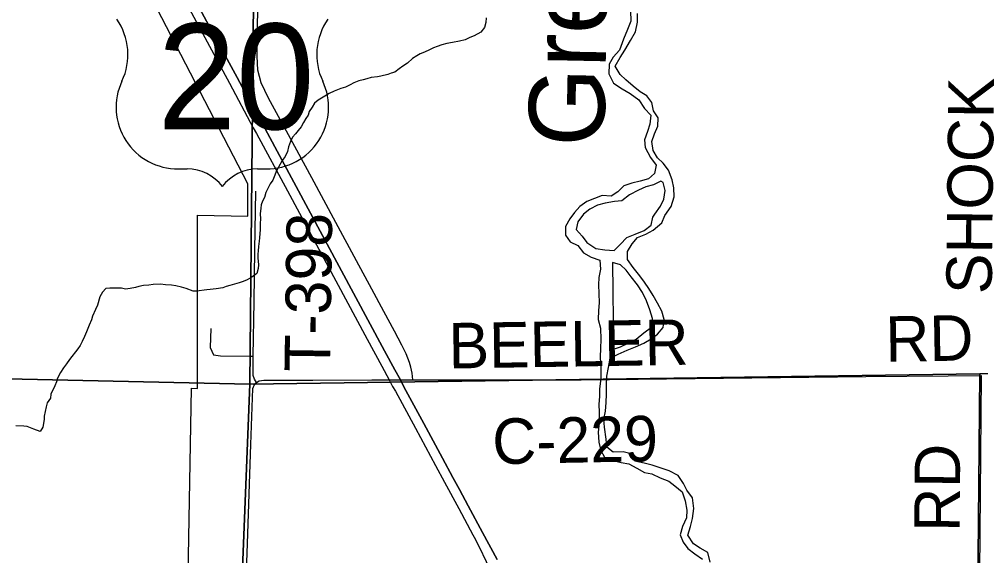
# Model space of a CAD drawing. Extents: x 0 to 34, y 0 to 22.
# Drawn here: x 25.81 to 27.011, y 19.609 to 20.279 of the extents above; entities that cross this region are included whole.
import ezdxf

# ---------------------------------------------------------------- set-up
doc = ezdxf.new("R2010")
doc.units = 0
for name, color, linetype in [('GM_X_City_Street', 7, 'Continuous'), ('GM_X_County_Road', 7, 'Continuous'), ('GM_X_County_Road_Text', 7, 'Continuous'), ('GM_X_Minor_River', 7, 'Continuous'), ('GM_X_Minor_River_Text', 7, 'Continuous'), ('GM_X_Section', 7, 'Continuous'), ('GM_X_State_Route', 7, 'Continuous'), ('GM_X_Township_Road', 7, 'Continuous'), ('GM_X_Township_Road_Text', 7, 'Continuous'), ('GM_X_US_Location', 7, 'Continuous'), ('GM_X_US_Route', 7, 'Continuous'), ('GM_X_US_Shield', 7, 'Continuous')]:
    doc.layers.add(name, color=color, linetype=linetype)

msp = doc.modelspace()

# ---------------------------------------------------------------- linework, layer by layer
at = {"layer": 'GM_X_City_Street'}
msp.add_lwpolyline([(25.7608, 19.5385), (26.0181, 19.4449), (26.0246, 19.8182), (26.0322, 19.818), (26.0322, 20.0343), (26.0952, 20.0332), (26.0952, 20.0736), (25.9699, 20.3158)], dxfattribs=at)
at = {"layer": 'GM_X_County_Road'}
for points in [[(26.301, 19.8288), (26.3002, 19.8371), (26.2987, 19.8445), (26.2969, 19.8503), (26.2927, 19.8612), (26.2875, 19.8718), (26.2782, 19.8896), (26.2651, 19.9141), (26.25, 19.9419), (26.2307, 19.9774), (26.2049, 20.0253), (26.1749, 20.0809), (26.146, 20.1344), (26.121, 20.1805), (26.1119, 20.1994), (26.1076, 20.2154), (26.1067, 20.2326), (26.1076, 20.2958)], [(26.301, 19.8288), (26.5115, 19.8289), (26.8669, 19.8327), (26.9698, 19.8338), (27.0117, 19.8339)], [(26.0866, 19.4072), (26.089, 19.4486), (26.0905, 19.5054), (26.0945, 19.6244), (26.0989, 19.7481), (26.1013, 19.8177), (26.1022, 19.82)], [(26.1022, 19.82), (26.1025, 19.8208), (26.103, 19.8219), (26.106, 19.8254), (26.1091, 19.8275), (26.1149, 19.8284), (26.1762, 19.8284), (26.2498, 19.8286), (26.2717, 19.8289), (26.2857, 19.8286), (26.301, 19.8288)]]:
    msp.add_lwpolyline(points, dxfattribs=at)
at = {"layer": 'GM_X_Minor_River'}
msp.add_line((26.5505, 19.9752), (26.5517, 19.8669), dxfattribs=at)
for points in [[(26.573, 20.2893), (26.5734, 20.2764), (26.5693, 20.2659), (26.5641, 20.2542), (26.5592, 20.2403), (26.5513, 20.2314), (26.5465, 20.2228), (26.5458, 20.2107), (26.552, 20.1991), (26.5628, 20.192), (26.5725, 20.186), (26.5833, 20.1782), (26.5905, 20.1673), (26.5983, 20.1591), (26.5972, 20.1478), (26.5943, 20.1387), (26.5906, 20.1282), (26.5915, 20.1187), (26.598, 20.1064), (26.6053, 20.0967), (26.6032, 20.0865), (26.5954, 20.0795), (26.5851, 20.0767), (26.5748, 20.0743), (26.5648, 20.0708), (26.5574, 20.0634), (26.5489, 20.058), (26.5376, 20.059), (26.528, 20.0551), (26.5184, 20.0512), (26.5099, 20.045), (26.5029, 20.0376), (26.4973, 20.0298), (26.4918, 20.0201), (26.4919, 20.0094), (26.4977, 20.0009), (26.5074, 19.9965), (26.5144, 19.9872), (26.5241, 19.982), (26.5346, 19.9782), (26.5354, 19.9668), (26.5337, 19.9566), (26.533, 19.9472), (26.5335, 19.9365), (26.5339, 19.9247), (26.5329, 19.9153), (26.5326, 19.9039), (26.5354, 19.8932), (26.5361, 19.8791), (26.5354, 19.8681), (26.5351, 19.8571), (26.5359, 19.843), (26.5359, 19.8305), (26.5344, 19.8176), (26.5342, 19.8082), (26.5335, 19.7979), (26.534, 19.7884), (26.5341, 19.7751)], [(26.3929, 20.2807), (26.3924, 20.275), (26.3905, 20.2686), (26.3862, 20.2626), (26.3778, 20.2581), (26.3725, 20.2563), (26.3664, 20.2533), (26.3595, 20.2515), (26.3508, 20.2497), (26.3436, 20.2486), (26.3375, 20.2468), (26.3314, 20.2449), (26.3268, 20.2431), (26.3219, 20.2409), (26.3158, 20.2379), (26.3104, 20.2357), (26.3062, 20.2331), (26.3009, 20.2301), (26.2947, 20.2241), (26.2886, 20.2203), (26.284, 20.217), (26.2787, 20.2128), (26.2741, 20.2114), (26.2699, 20.2099), (26.2612, 20.2077), (26.257, 20.207), (26.249, 20.206), (26.2437, 20.2045), (26.2391, 20.2034), (26.2338, 20.2019), (26.2273, 20.1994), (26.2227, 20.1971), (26.217, 20.1941), (26.2113, 20.1923), (26.2071, 20.1908), (26.2029, 20.189), (26.1968, 20.1864), (26.1892, 20.1815), (26.1831, 20.1778), (26.1785, 20.1741), (26.1754, 20.1692), (26.1715, 20.1639), (26.1703, 20.1593), (26.1676, 20.1548), (26.1645, 20.1499), (26.1618, 20.1446), (26.158, 20.1401), (26.1545, 20.136), (26.1507, 20.1318), (26.1483, 20.1262), (26.146, 20.1194), (26.1444, 20.1137), (26.1417, 20.1076), (26.1378, 20.1024), (26.1332, 20.0941)], [(26.5638, 19.739), (26.5516, 19.7382), (26.5435, 19.7445), (26.5426, 19.7548), (26.5404, 19.7696), (26.5399, 19.7795), (26.542, 19.7897), (26.5427, 19.8003), (26.543, 19.8109), (26.5429, 19.822), (26.5436, 19.8333), (26.5454, 19.8439), (26.5476, 19.8556), (26.5576, 19.8607), (26.5687, 19.8657), (26.5795, 19.8699), (26.5898, 19.8746), (26.5987, 19.88), (26.6068, 19.8859), (26.6139, 19.8941), (26.6153, 19.9039), (26.6122, 19.9146), (26.6067, 19.9246), (26.6013, 19.9339), (26.5959, 19.9428), (26.5904, 19.9505), (26.5849, 19.9586), (26.5765, 19.9691), (26.5695, 19.9788), (26.5694, 19.9891), (26.575, 19.9984), (26.5816, 20.0062), (26.5924, 20.0105), (26.6012, 20.0155), (26.6121, 20.0247), (26.6158, 20.0337), (26.624, 20.0449), (26.6274, 20.0573), (26.6273, 20.0683), (26.6253, 20.0783), (26.6207, 20.0906), (26.6137, 20.0991), (26.6067, 20.1057), (26.6013, 20.115), (26.5997, 20.1264), (26.603, 20.1358), (26.607, 20.1452), (26.6077, 20.1558), (26.6018, 20.1644), (26.5995, 20.1751), (26.5936, 20.1832), (26.5851, 20.1884), (26.5765, 20.1954), (26.5673, 20.2033), (26.5602, 20.2099), (26.5541, 20.2203), (26.56, 20.2312), (26.566, 20.2401), (26.5731, 20.2525), (26.5791, 20.2633), (26.5817, 20.2754), (26.582, 20.286)], [(26.1332, 20.0941), (26.1305, 20.0888), (26.1289, 20.0842), (26.1262, 20.0778), (26.1231, 20.0733), (26.1204, 20.0684), (26.1176, 20.0624), (26.1157, 20.0563), (26.1134, 20.0518), (26.1118, 20.0472), (26.1114, 20.0431), (26.1105, 20.0359), (26.1108, 20.0298), (26.1104, 20.0237), (26.1103, 20.0161), (26.1099, 20.0116), (26.1098, 20.0059), (26.1094, 20.0017), (26.1085, 19.9953), (26.1081, 19.9899), (26.1077, 19.9858), (26.1076, 19.9808), (26.1079, 19.9767), (26.1083, 19.9721), (26.1078, 19.9676), (26.1063, 19.9615), (26.1001, 19.957), (26.0944, 19.9537), (26.0891, 19.9514), (26.0841, 19.9496), (26.0784, 19.9481), (26.0727, 19.9463), (26.0681, 19.9452), (26.0639, 19.9437), (26.0556, 19.9423), (26.048, 19.9416), (26.0438, 19.9409), (26.0309, 19.9395), (26.0267, 19.9396), (26.018, 19.9427), (26.012, 19.9443), (26.0052, 19.9459), (25.9995, 19.9467), (25.9923, 19.9472), (25.9859, 19.948), (25.9767, 19.9477), (25.9714, 19.947), (25.9646, 19.9463), (25.9589, 19.9452), (25.9547, 19.9441), (25.9482, 19.9427), (25.9422, 19.942), (25.9372, 19.9432), (25.9228, 19.9433), (25.9175, 19.9426), (25.9137, 19.9381), (25.9102, 19.9325), (25.9074, 19.9219), (25.9047, 19.9166), (25.9012, 19.9083), (25.8996, 19.9034), (25.8969, 19.8969), (25.8934, 19.8886), (25.891, 19.8826), (25.8883, 19.8765), (25.8856, 19.8716), (25.8825, 19.8675), (25.8725, 19.8539), (25.8686, 19.8486), (25.8648, 19.8438), (25.8609, 19.8377), (25.8574, 19.8309), (25.8559, 19.8264), (25.8539, 19.8211), (25.8489, 19.8109), (25.8484, 19.8056), (25.8442, 19.7999), (25.843, 19.795), (25.8418, 19.789), (25.8406, 19.7833), (25.8405, 19.7791), (25.8389, 19.7696), (25.8358, 19.7643), (25.8279, 19.7671), (25.8196, 19.7706), (25.8154, 19.771), (25.8052, 19.7711)], [(26.6109, 20.0768), (26.6016, 20.0721), (26.5921, 20.0697), (26.5829, 20.0654), (26.5717, 20.0596), (26.5624, 20.0523), (26.5529, 20.0514), (26.5415, 20.0491), (26.5319, 20.0467), (26.5223, 20.0416), (26.5142, 20.0354), (26.5071, 20.0261), (26.5053, 20.0163), (26.5127, 20.0081), (26.5185, 20), (26.5297, 19.9928), (26.541, 19.991), (26.5528, 19.9903), (26.5602, 19.9977), (26.5684, 20.0066), (26.5787, 20.0104), (26.5902, 20.0151), (26.5988, 20.022), (26.6009, 20.0319), (26.6033, 20.0356)], [(26.6033, 20.0356), (26.6104, 20.0457), (26.6148, 20.0543), (26.6162, 20.0652), (26.6138, 20.0752), (26.6109, 20.0768)], [(26.5517, 19.8669), (26.5605, 19.8697), (26.5701, 19.8744), (26.5801, 19.8794), (26.5898, 19.8875), (26.5991, 19.8945), (26.6005, 19.9051), (26.597, 19.9162), (26.5932, 19.9273), (26.5881, 19.9377), (26.5816, 19.9473), (26.5739, 19.9574), (26.5676, 19.9656), (26.5606, 19.9722), (26.5505, 19.9752)], [(26.5341, 19.7751), (26.5326, 19.7634), (26.5334, 19.7508), (26.5358, 19.7405), (26.5405, 19.732), (26.551, 19.728), (26.5615, 19.7254), (26.571, 19.724), (26.5811, 19.7184), (26.5904, 19.7132), (26.5998, 19.7114), (26.6099, 19.7062), (26.6208, 19.7021), (26.6286, 19.6962), (26.6375, 19.6887), (26.6414, 19.6776), (26.6433, 19.6658), (26.6431, 19.6563), (26.6382, 19.6454), (26.6349, 19.6353), (26.6389, 19.6261), (26.6447, 19.6183), (26.6536, 19.6116), (26.6629, 19.6049)], [(26.6727, 19.6012), (26.6696, 19.6131), (26.6599, 19.6186), (26.6517, 19.6238), (26.6448, 19.6346), (26.6481, 19.6455), (26.6503, 19.6557), (26.6521, 19.6682), (26.6506, 19.6812), (26.6436, 19.6909), (26.6393, 19.6993), (26.6324, 19.7094), (26.6212, 19.715), (26.6114, 19.7183), (26.6001, 19.722), (26.5903, 19.7246), (26.5786, 19.7272), (26.574, 19.7361), (26.5638, 19.739)]]:
    msp.add_lwpolyline(points, dxfattribs=at)
at = {"layer": 'GM_X_Section'}
for points in [[(27.0582, 20.8419), (27.044, 19.8365), (27.0095, 19.8363), (26.0975, 19.8234), (26.1071, 20.822)], [(26.1064, 20.8349), (26.1071, 20.822), (26.0975, 19.8234), (25.0925, 19.8455), (25.1198, 20.8277)], [(28.0159, 19.8585), (28.001, 18.9217), (27.0012, 18.9192), (27.0095, 19.8363), (27.044, 19.8365)], [(25.0077, 19.8483), (25.0925, 19.8455), (26.0975, 19.8234), (26.0616, 18.9227), (26.0607, 18.8928), (24.9624, 18.9716)], [(27.0095, 19.8363), (27.0012, 18.9192), (26.0616, 18.9227), (26.0975, 19.8234)]]:
    msp.add_lwpolyline(points, close=True, dxfattribs=at)
at = {"layer": 'GM_X_State_Route'}
for points in [[(26.2857, 19.8286), (26.2786, 19.8411), (26.2659, 19.8648), (26.1166, 20.142), (26.1018, 20.1688), (26.0817, 20.2061), (26.049, 20.2665), (25.9769, 20.4002), (25.8649, 20.6078), (25.8325, 20.6678), (25.819, 20.693)], [(26.4065, 19.6043), (26.3883, 19.6381), (26.3704, 19.6712), (26.3593, 19.6918), (26.3512, 19.7066), (26.3382, 19.7309), (26.3148, 19.7741), (26.29, 19.82), (26.2857, 19.8286)]]:
    msp.add_lwpolyline(points, dxfattribs=at)
at = {"layer": 'GM_X_Township_Road'}
msp.add_line((26.104, 19.9904), (26.1052, 20.0644), dxfattribs=at)
for points in [[(26.106, 19.8254), (26.1032, 19.8294), (26.1017, 19.8342), (26.1019, 19.8581), (26.1029, 19.9266), (26.104, 19.9904)], [(26.0488, 19.8926), (26.0482, 19.8691), (26.0521, 19.8597), (26.0609, 19.8586), (26.0984, 19.8581), (26.1019, 19.8581)], [(27.0042, 19.0768), (27.005, 19.173), (27.0061, 19.2969), (27.0091, 19.5392), (27.0117, 19.8339)]]:
    msp.add_lwpolyline(points, dxfattribs=at)
at = {"layer": 'GM_X_US_Route'}
for points in [[(25.8097, 20.6852), (25.823, 20.6607), (25.8518, 20.6071), (26.072, 20.1992), (26.1019, 20.1434), (26.1058, 20.1362), (26.1444, 20.0646)], [(25.819, 20.693), (25.8325, 20.6678), (25.8649, 20.6078), (25.9769, 20.4002), (26.049, 20.2665), (26.0817, 20.2061), (26.1018, 20.1688), (26.1166, 20.142), (26.2659, 19.8648), (26.2786, 19.8411), (26.2857, 19.8286)], [(26.1444, 20.0646), (26.2443, 19.8796), (26.2626, 19.8459), (26.2717, 19.8289)], [(26.2717, 19.8289), (26.2759, 19.8202), (26.2796, 19.8145), (26.3044, 19.7683), (26.3296, 19.7216), (26.3408, 19.7008), (26.3585, 19.6682), (26.3762, 19.635), (26.3777, 19.6323)], [(26.2857, 19.8286), (26.29, 19.82), (26.3148, 19.7741), (26.3382, 19.7309), (26.3512, 19.7066), (26.3593, 19.6918), (26.3704, 19.6712), (26.3883, 19.6381), (26.4065, 19.6043)], [(26.3777, 19.6323), (26.3839, 19.6203), (26.3926, 19.6017), (26.4013, 19.5806), (26.4087, 19.5583), (26.4127, 19.5433), (26.4141, 19.5374)]]:
    msp.add_lwpolyline(points, dxfattribs=at)
at = {"layer": 'GM_X_US_Shield'}
for p, q in [((26.0083, 20.0921), (26.0193, 20.0921)), ((26.1071, 20.0921), (26.1181, 20.0921))]:
    msp.add_line(p, q, dxfattribs=at)
for centre, radius, start, end in [((25.8684, 20.2348), 0.0769, 334.5471, 35.0009), ((26.258, 20.2348), 0.0769, 144.9991, 205.4529), ((26.0074, 20.169), 0.0769, 154.8319, 270.6383), ((26.119, 20.169), 0.0769, 269.3617, 25.1681), ((26.0193, 20.0372), 0.0549, 36.8699, 90), ((26.1071, 20.0372), 0.0549, 90, 143.1301)]:
    msp.add_arc(centre, radius, start, end, dxfattribs=at)

# ---------------------------------------------------------------- texts
at = {"layer": 'GM_X_County_Road_Text'}
for s, rotation, p in [('BEELER', 0.9092, (26.3462, 19.8428)), ('RD', 0.9872, (26.892, 19.8511)), ('C-229', 1.1016, (26.4009, 19.7233))]:
    msp.add_text(s, height=0.05682, rotation=rotation, dxfattribs=at).set_placement(p)
at = {"layer": 'GM_X_Minor_River_Text'}
msp.add_text('Green', height=0.09475, rotation=88.8302, dxfattribs=at).set_placement((26.54, 20.1191))
at = {"layer": 'GM_X_Township_Road_Text'}
for s, rotation, p in [('SHOCK', 89.39, (27.0242, 19.9355)), ('T-398', 89.1679, (26.1976, 19.8383)), ('RD', 89.5063, (26.9842, 19.6388))]:
    msp.add_text(s, height=0.05682, rotation=rotation, dxfattribs=at).set_placement(p)
at = {"layer": 'GM_X_US_Location'}
for s in ['0', '/']:
    msp.add_text(s, height=0.000189, dxfattribs=at).set_placement((26.0631, 20.2065))
msp.add_text('20', height=0.000189, rotation=0, dxfattribs=at).set_placement((26.024, 20.1673))
at = {"layer": 'GM_X_US_Shield'}
msp.add_text('20', height=0.13184, dxfattribs=at).set_placement((25.9823, 20.1416))

doc.saveas('drawing.dxf')
